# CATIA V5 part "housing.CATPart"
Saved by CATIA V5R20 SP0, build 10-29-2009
Part number: housing
Bounding box of the stored display mesh (mm): x -22.5 to 22.5, y -80 to 17.995, z -45 to 106
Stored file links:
  D:\Documents and Settings\mosavian\My Documents\DMU Project3\New Folder\housing.CATPart
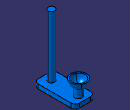
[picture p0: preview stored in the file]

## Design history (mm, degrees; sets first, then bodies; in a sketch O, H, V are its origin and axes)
Body1 (main body)
  Sketch1 on yz-plane, origin (0, 0, 0), H (0, 1, 0), V (0, 0, 1)
    arc A1 centre (0, 0) radius 15 from (0, -15) to (15, 0) ccw
    point P1 (15, 0)
    point P2 (0, -15)
    arc A2 centre (0, 0) radius 18 from (0, -18) to (18, 0) ccw
    point P3 (18, 0)
    point P4 (0, -18)
    line L1 (15, 0) -> (18, 0)
    line L2 (0, -15) -> (0, -18)
    radius A2 = 18
    radius A1 = 15
    coincidence: P1 H, P2 V, P3 H, P4 V
    horizontal: L1 H
    vertical: L2 V
  Shaft1: profile Sketch1, axis Sketch1.L2, angle 360
  Sketch2 on yz-plane, origin (0, 0, 0), H (0, 1, 0), V (0, 0, 1)
    point P1 (0, -15)
    line L1 (0, -15) -> (8, -15)
    line L2 (8, -15) -> (8, -35)
    line L3 (8, -35) -> (0, -35)
    axis line L4 (0, -35) -> (0, -15)
    distance L1 H = 15
    length L3 = 8
    length L2 = 20
    coincidence: P1 V
    horizontal: L1 H, L3 H
    vertical: L2 V, L4 V
  Shaft2: profile Sketch2, axis Sketch2.L4, angle 360
  Sketch3 on face of Shaft2 from Sketch2.L3, origin (0, 0, -35), H (1, 0, 0), V (0, -1, 0)
    point P1 (0, 32.5)
    line L1 (22.5, 80) -> (22.5, -15)
    line L2 (22.5, -15) -> (-22.5, -15)
    line L3 (-22.5, -15) -> (-22.5, 80)
    line L4 (-22.5, 80) -> (22.5, 80)
    distance L2 H = 15
    distance H L4 = 80
    length L4 = 45
    coincidence: P1 V
    vertical: L1 V, L3 V
    horizontal: L2 H, L4 H
    equidistance: L1 L3 P1, L2 L4 P1
  Pad1: profile Sketch3, direction (0, 0, -1), length 10
  Fillet1: radius 10, on edge [face of Pad1 from Sketch3.L1 | face of Pad1 from Sketch3.L2]; edge [face of Pad1 from Sketch3.L4 | face of Pad1 from Sketch3.L1]; edge [face of Pad1 from Sketch3.L3 | face of Pad1 from Sketch3.L4]; edge [face of Pad1 from Sketch3.L2 | face of Pad1 from Sketch3.L3]
  Sketch4 on start face of Pad1, origin (0, 0, -35), H (1, 0, 0), V (0, 1, 0)
    circle A1 centre (0, -62) radius 7.5
    point P1 (0, -62)
    radius A1 = 7.5
    distance P1 H = 62
    coincidence: P1 V
  Pad2: profile Sketch4, direction (0, 0, 1), length 141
